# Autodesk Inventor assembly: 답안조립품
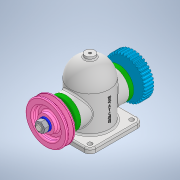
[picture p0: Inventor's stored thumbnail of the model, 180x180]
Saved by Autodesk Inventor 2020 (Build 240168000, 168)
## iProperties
Created: 2021-07
Part Number: 답안조립품
Document SubType Name: Assembly
Designer: Owner
Author: Owner
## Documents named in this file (14)
- C:\Users\Owner\Desktop\710716V1007\답안조립품.iam
- C:\Users\Owner\Desktop\710716V1007\본체.ipt
- C:\Users\Owner\Desktop\710716V1007\V-벨트풀리.ipt
- V-벨트풀리.ipt
- C:\Users\Owner\Desktop\710716V1007\너트 M12x1.25.ipt
- C:\Users\Owner\Desktop\710716V1007\베어링 6203.ipt
- C:\Users\Owner\Desktop\710716V1007\볼트 M4.ipt
- C:\Users\Owner\Desktop\710716V1007\부시.ipt
- C:\Users\Owner\Desktop\710716V1007\스퍼기어.ipt
- C:\Users\Owner\Desktop\710716V1007\오일 실 26 38 8.ipt
- C:\Users\Owner\Desktop\710716V1007\와셔 12x24.ipt
- C:\Users\Owner\Desktop\710716V1007\축.ipt
- C:\Users\Owner\Desktop\710716V1007\커버.ipt
- C:\Users\Owner\Desktop\710716V1007\키 5x5x12.ipt
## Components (1 placed, 1 different names)
1. V-벨트풀리:1
